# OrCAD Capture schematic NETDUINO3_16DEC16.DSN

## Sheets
1 PAGE2: size C; note: CW0057
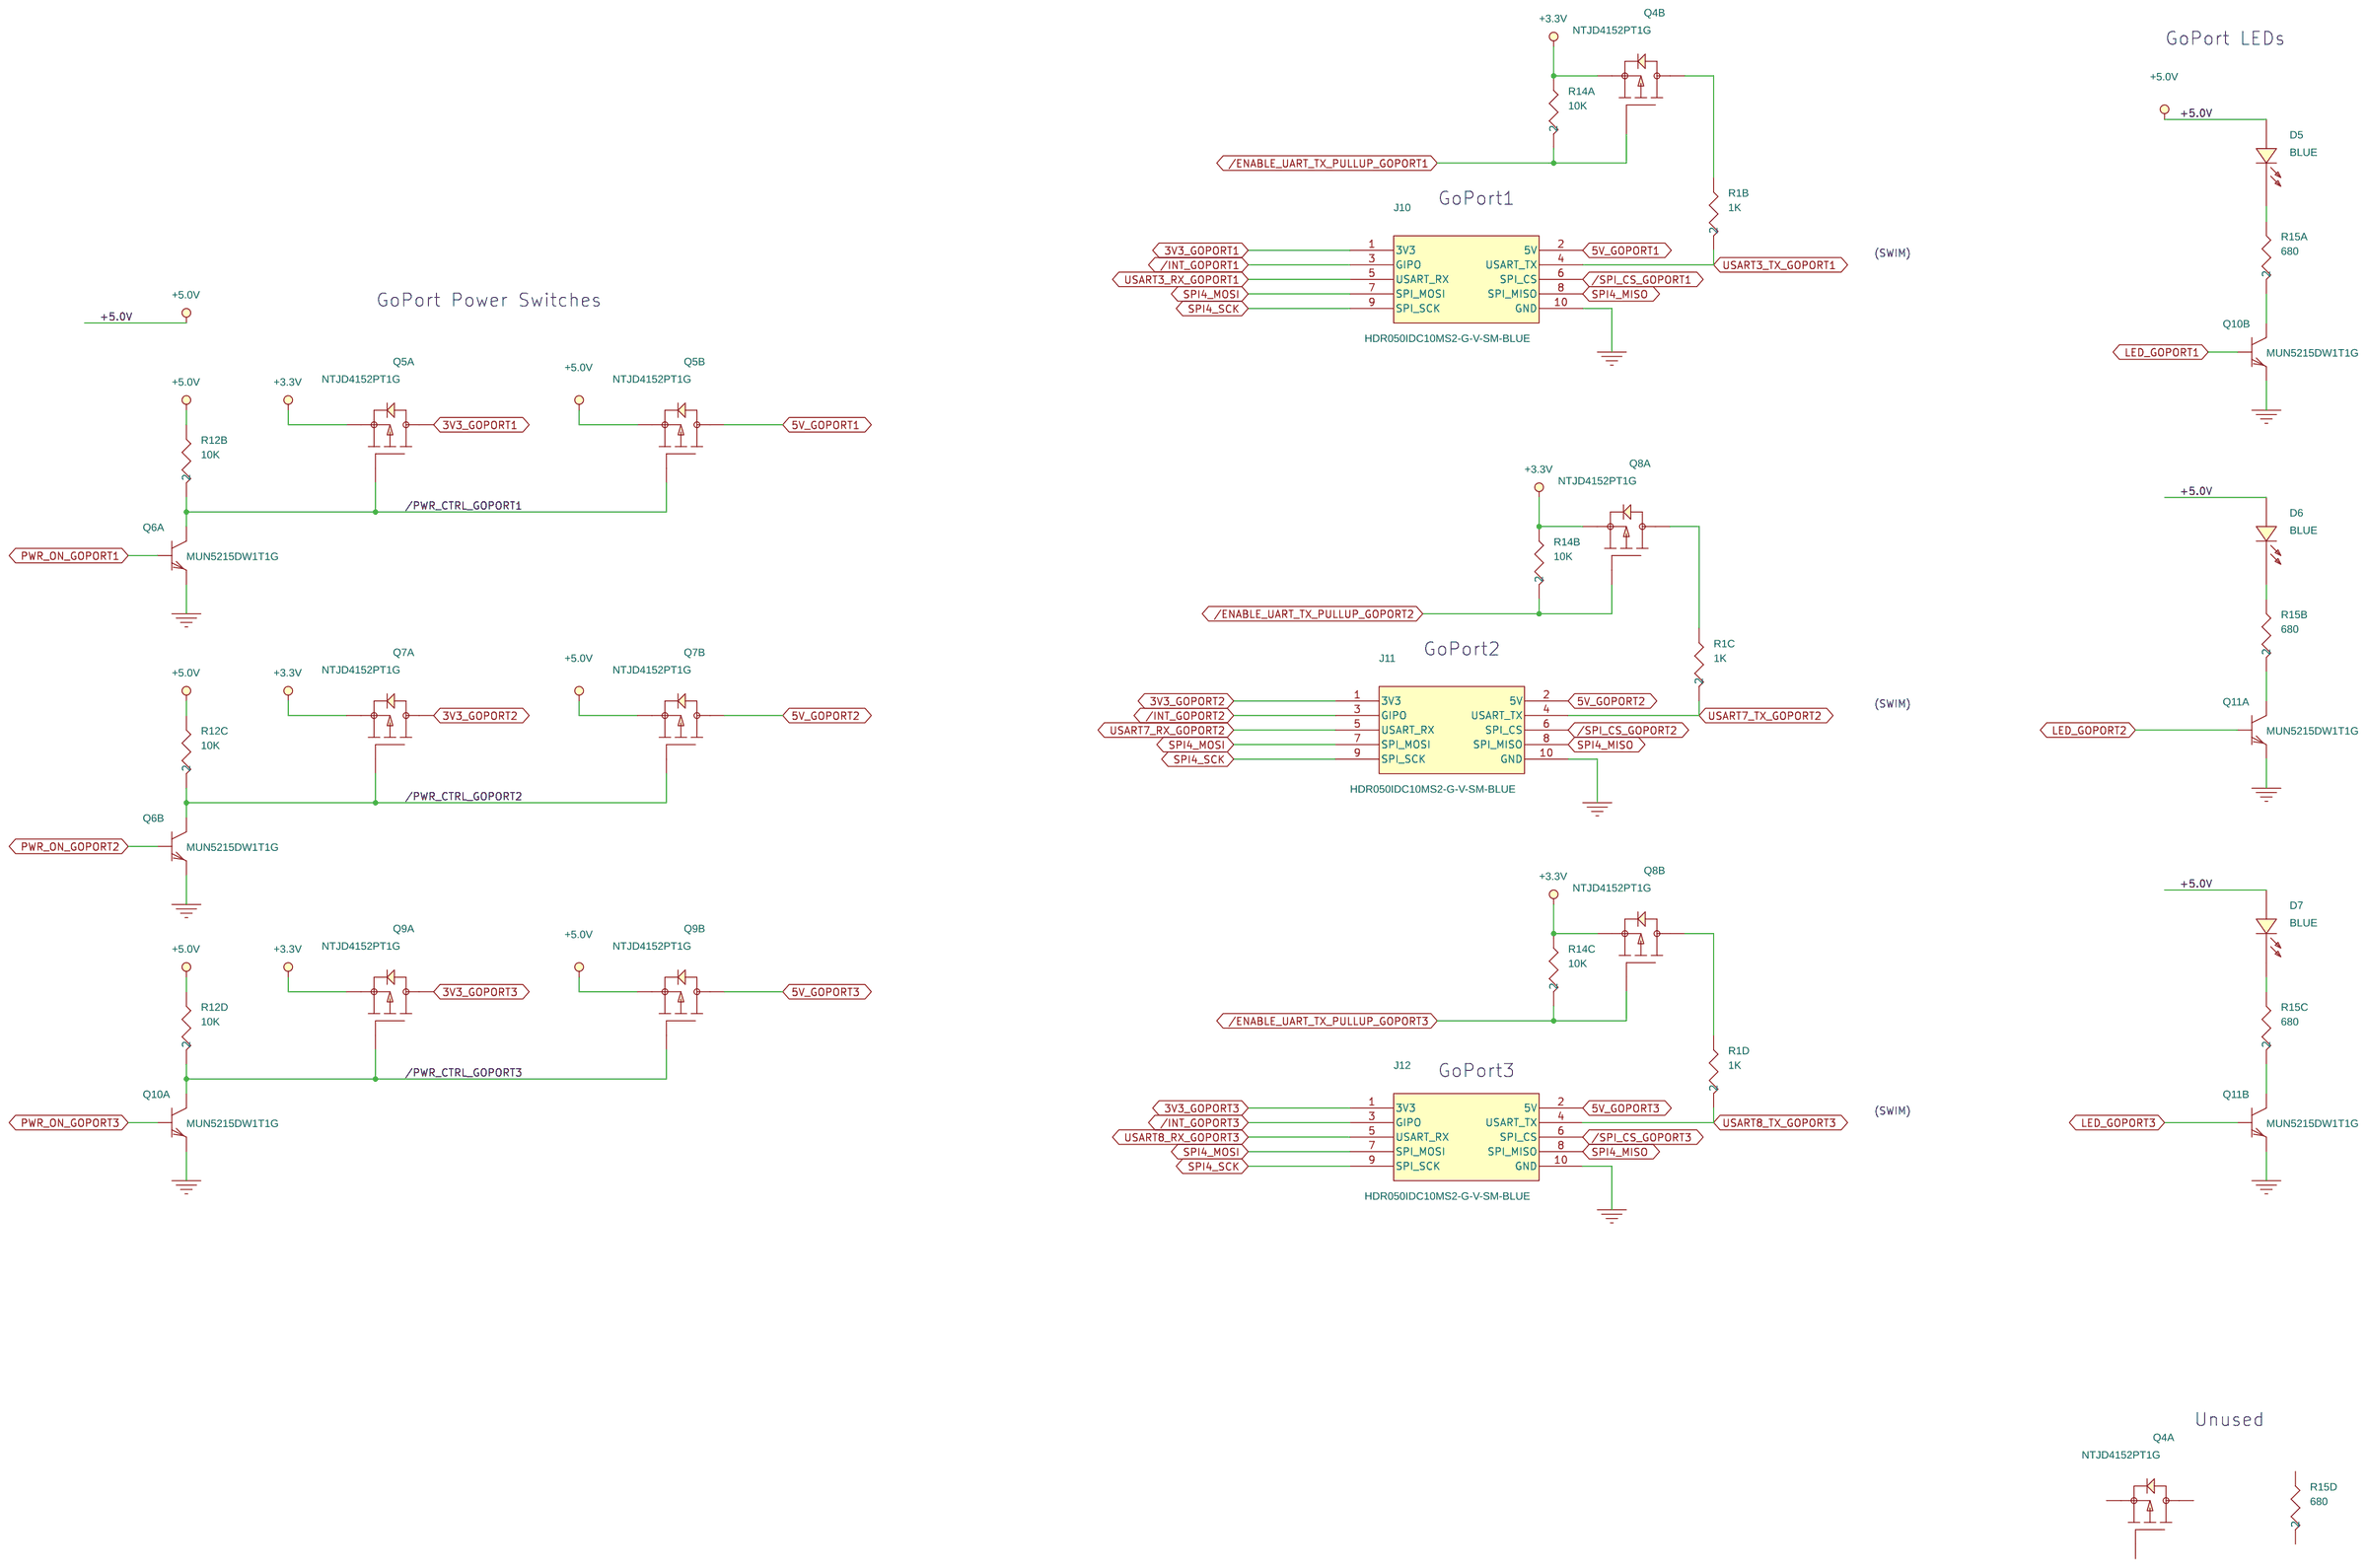
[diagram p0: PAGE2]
2 PAGE1: size C
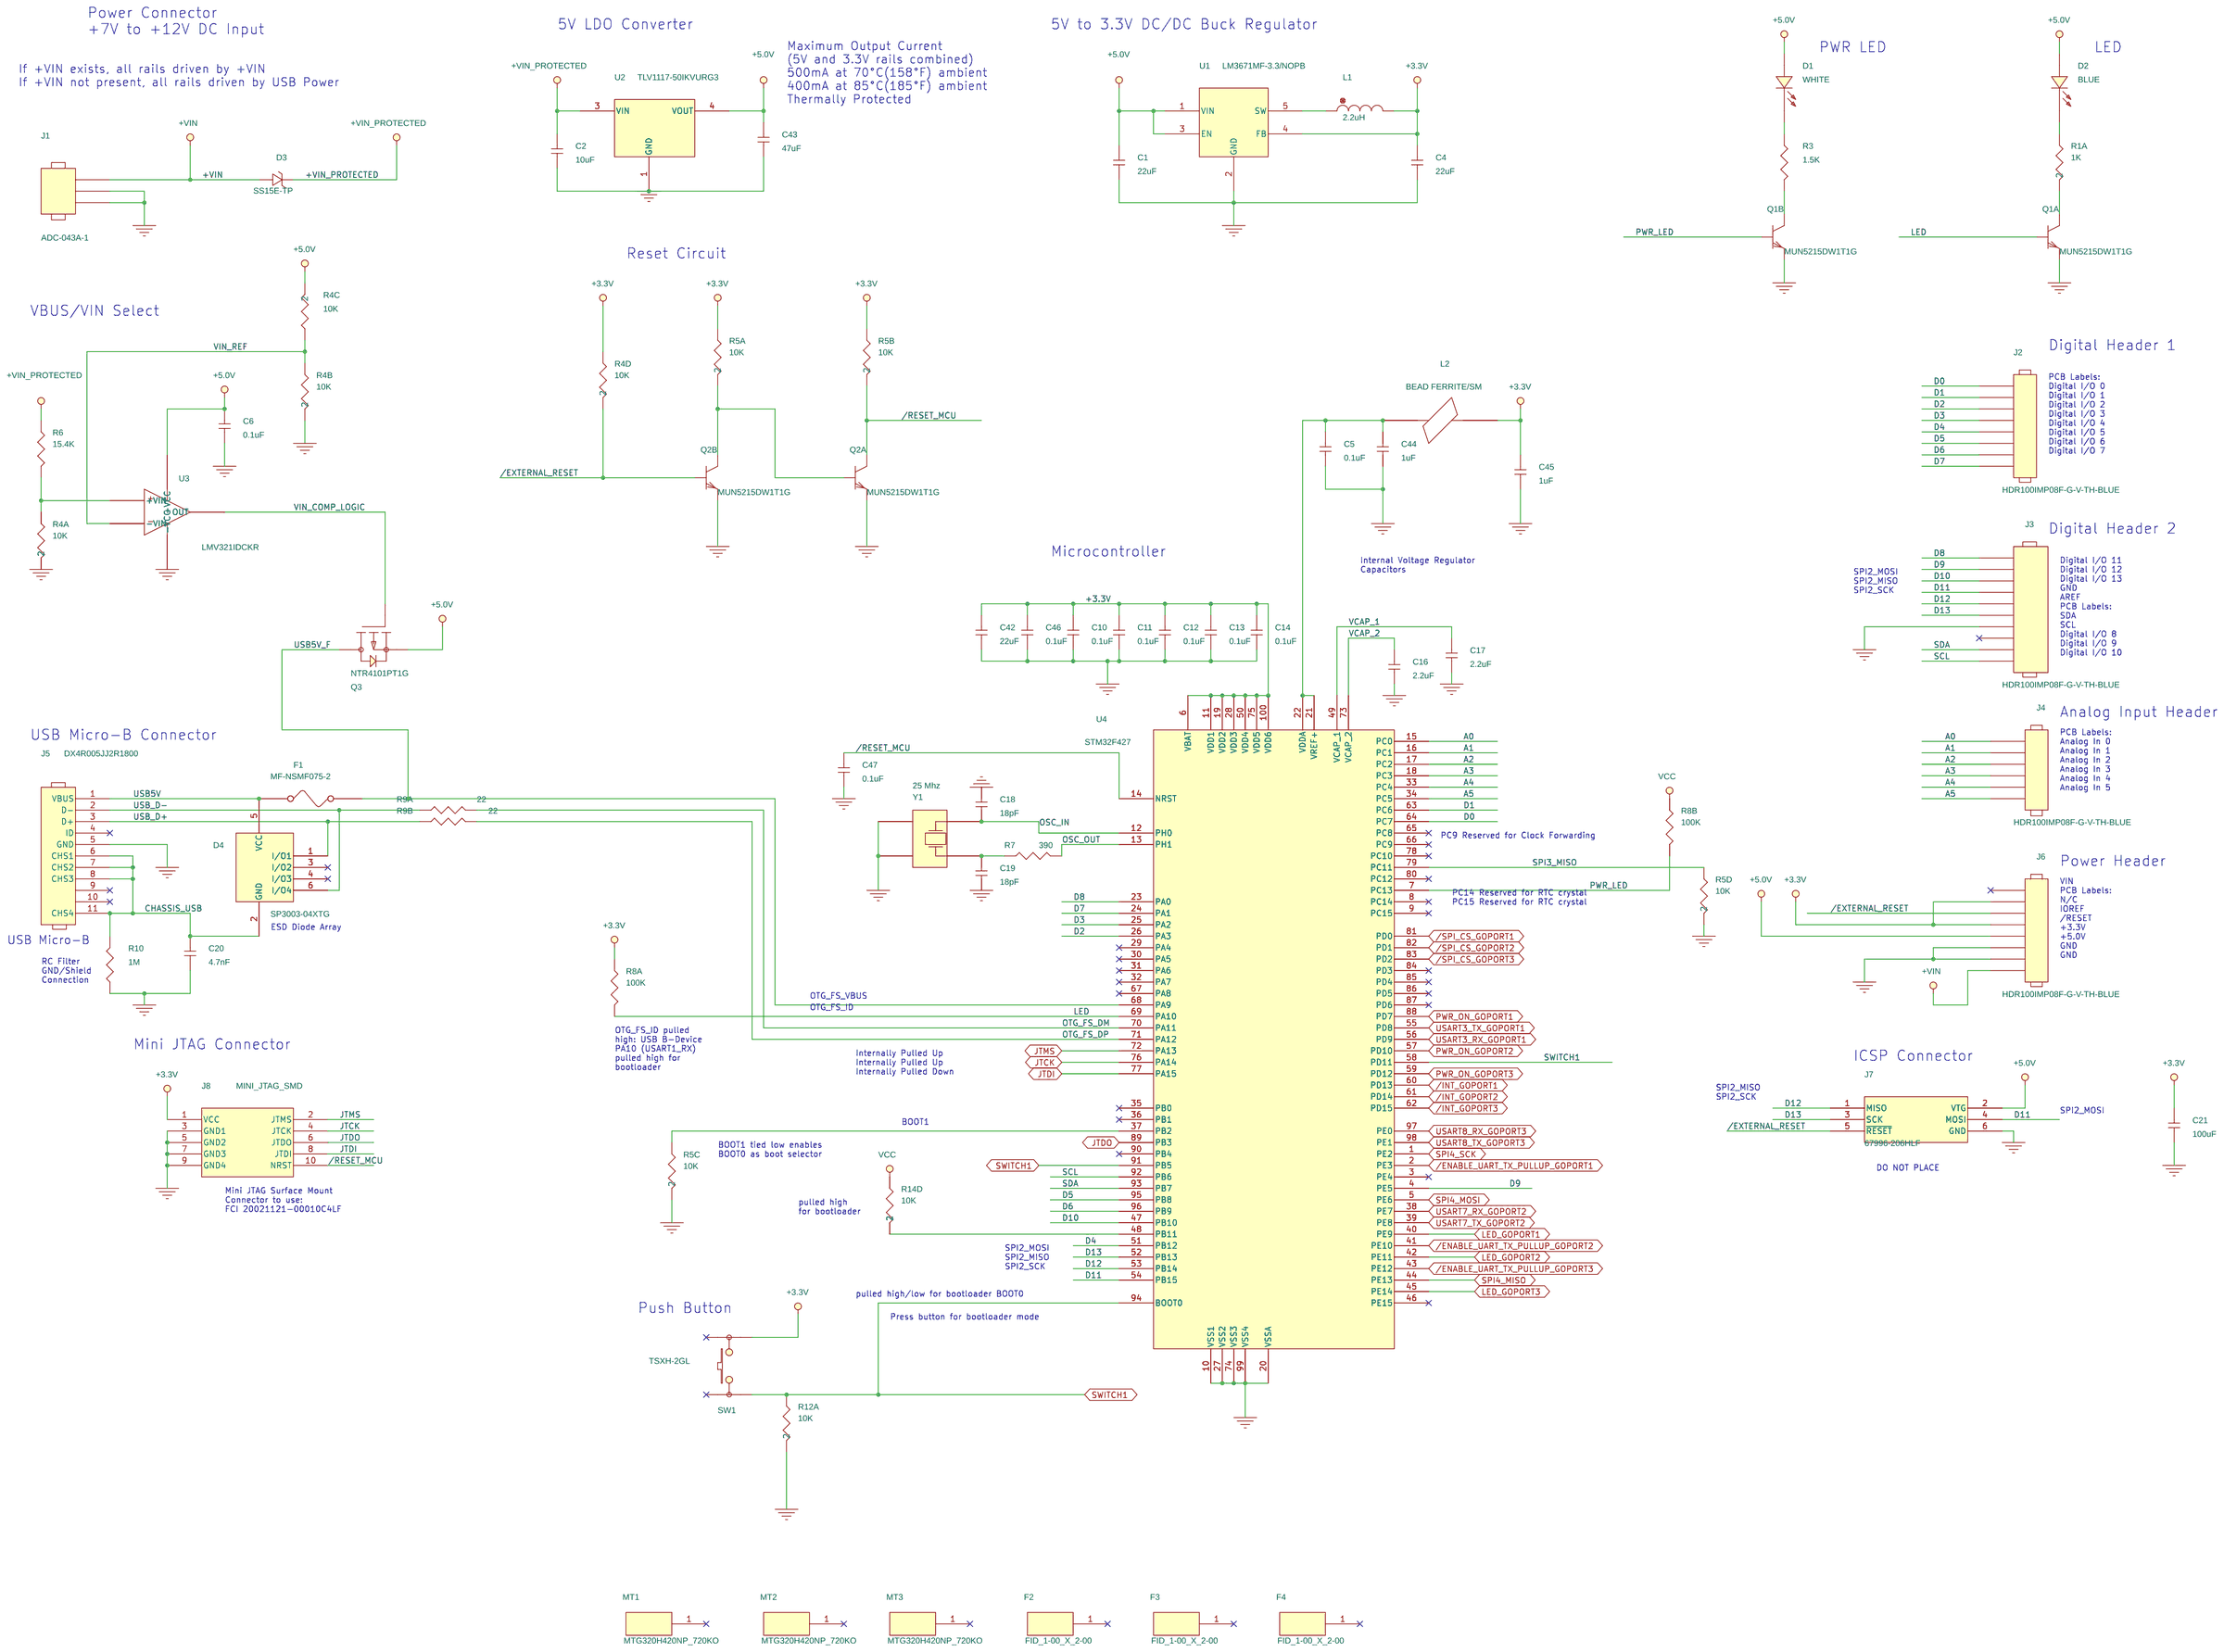
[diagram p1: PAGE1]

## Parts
sheet PAGE1
C1  22uF  [CAPC3216X180N]
C2  10uF  [CAPC2012X125N]
C4  22uF  [CAPC2012X125N]
C5  0.1uF  [CAPC1608X90N]
C6  0.1uF  [CAPC1608X90N]
C10  0.1uF  [CAPC1608X90N]
C11  0.1uF  [CAPC1608X90N]
C12  0.1uF  [CAPC1608X90N]
C13  0.1uF  [CAPC1608X90N]
C14  0.1uF  [CAPC1608X90N]
C16  2.2uF  [CAPC1608X90N]
C17  2.2uF  [CAPC1608X90N]
C18  18pF  [CAPC1608X90N]
C19  18pF  [CAPC1608X90N]
C20  4.7nF  [CAPC1005X55N]
C21  100uF  [CAPMP6032X280N]
C42  22uF  [CAPC2012X125N]
C43  47uF  [F931A476MBA]
C44  1uF  [CAPC1005X55N]
C45  1uF  [CAPC1005X55N]
C46  0.1uF  [CAPC1608X90N]
C47  0.1uF  [CAPC1608X90N]
D1  WHITE  [LEDC2012X110N]
D2  BLUE  [LEDC2012X110N]
D3  SS15E-TP  [SS15-TP]
D4  SP3003-04XTG  [SP3003-04XTG]
F1  MF-NSMF075-2  [RESC3216X100N]
F2  FID_1-00_X_2-00  [FID_1-00_X_2-00]
F3  FID_1-00_X_2-00  [FID_1-00_X_2-00]
F4  FID_1-00_X_2-00  [FID_1-00_X_2-00]
J1  ADC-043A-1  [ADC-002A-1]
J2  HDR100IMP08F-G-V-TH-BLUE  [HDR100IMP08F-G-V-TH]
J3  HDR100IMP08F-G-V-TH-BLUE  [HDR100IMP10F-G-V-TH]
J4  HDR100IMP08F-G-V-TH-BLUE  [HDR100IMP06F-G-V-TH]
J5  DX4R005JJ2R1800  [DX4R005JJ2R1800]
J6  HDR100IMP08F-G-V-TH-BLUE  [HDR100IMP08F-G-V-TH]
J7  67996-206HLF  [67996-206HLF]
J8  MINI_JTAG_SMD  [MINI_JTAG_SMD]
L1  2.2uH  [LQH3NPN2R2NM0L]
L2  BEAD FERRITE/SM  [INDC1005X55N]
MT1  MTG320H420NP_720KO  [MTG320H420NP_720KO]
MT2  MTG320H420NP_720KO  [MTG320H420NP_720KO]
MT3  MTG320H420NP_720KO  [MTG320H420NP_720KO]
Q1  MUN5215DW1T1G  [MUN5215DW1T1G]  (sections A,B)
Q2  MUN5215DW1T1G  [MUN5215DW1T1G]  (sections A,B)
Q3  NTR4101PT1G  [NTR4101PT1G]
R1  1K  [RESCAV50P80X160X60-8N]  (sections A,B,C,D)
R3  1.5K  [RESC1608]
R4  10K  [RESCAV80P160X320X70-8N]  (sections A,B,C,D)
R5  10K  [RESCAV80P160X320X70-8N]  (sections A,B,C,D)
R6  15.4K  [CAPC1005X55N]
R7  390  [CAPC1005X55N]
R8  100K  [EXB24V]  (sections A,B)
R9  22  [EXB24V]  (sections A,B)
R10  1M  [RESC1608]
R12  10K  [RESCAV80P160X320X70-8N]  (sections A,B,C,D)
R14  10K  [RESCAV80P160X320X70-8N]  (sections A,B,C,D)
SW1  TSXH-2GL  [TSXH-2GL]
U1  LM3671MF-3.3/NOPB  [LM3671MF]
U2  TLV1117-50IKVURG3  [TLV1117-50IKVURG3]
U3  LMV321IDCKR  [LMV321IDCKR]
U4  STM32F427  [STM32F427VIT6]
Y1  25 Mhz  [ABM3B]
sheet PAGE2
D5  BLUE  [LEDC1608X80N]
D6  BLUE  [LEDC1608X80N]
D7  BLUE  [LEDC1608X80N]
J10  HDR050IDC10MS2-G-V-SM-BLUE  [20021521-00010T1LF]
J11  HDR050IDC10MS2-G-V-SM-BLUE  [20021521-00010T1LF]
J12  HDR050IDC10MS2-G-V-SM-BLUE  [20021521-00010T1LF]
Q4  NTJD4152PT1G  [NTJD4152PT1G]  (sections A,B)
Q5  NTJD4152PT1G  [NTJD4152PT1G]  (sections A,B)
Q6  MUN5215DW1T1G  [MUN5215DW1T1G]  (sections A,B)
Q7  NTJD4152PT1G  [NTJD4152PT1G]  (sections A,B)
Q8  NTJD4152PT1G  [NTJD4152PT1G]  (sections A,B)
Q9  NTJD4152PT1G  [NTJD4152PT1G]  (sections A,B)
Q10  MUN5215DW1T1G  [MUN5215DW1T1G]  (sections A,B)
Q11  MUN5215DW1T1G  [MUN5215DW1T1G]  (sections A,B)
R15  680  [RESCAV50P80X160X60-8N]  (sections A,B,C,D)

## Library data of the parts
C1 C2 C4-C6 C10-C14 C16-C21 C42-C47 = C
D1 = LED_2
D2 D5-D7 = LED_1
D3 = D05AZ75_0
D4 = HEADER_6_0
F1 = FUSE
F2-F4 MT1-MT3 = MOUNT_HOLE
J1 = HEADER_3
J2 J6 = HEADER_8
J3 = HEADER_10
J4 = HEADER_6
J5 = HEADER_11_0
J7 = HEADER_6_1
J8 = HEADER_10_2_v2
L1 = L
L2 = BEAD_FERRITE_SM
Q1 Q2 = MUN5215DW1T1G_3
Q3 = NDF0610_TO_1
R1 R4 R5 R12 R14 R15 = RESCAV50P80X160X60-8N
R3 R6 R7 R10 = R
R8 R9 = EXB24V
SW1 = SW_PUSHBUTTON-SPST-2_0
U1 = HEADER_5_0
U2 = LM7805_TO_2
U3 = LMV321_SO
U4 = STM32F427_0
Y1 = OSC_XF: MPN: ABM3B-25.000MHZ-D2Y-T; Manufacturer: Abracon Corporation
J10-J12 = HEADER_10_2
Q4 Q5 Q7-Q9 = NTJD4152PT1G
Q6 Q10 Q11 = MUN5215DW1T1G_0

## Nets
3V3_GOPORT1: J10.1(3V3) Q5.6(DRAIN)
3V3_GOPORT2: J11.1(3V3) Q7.6(DRAIN)
3V3_GOPORT3: J12.1(3V3) Q9.6(DRAIN)
5V_GOPORT1: J10.2(5V) Q5.3(DRAIN)
5V_GOPORT2: J11.2(5V) Q7.3(DRAIN)
5V_GOPORT3: J12.2(5V) Q9.3(DRAIN)
+3.3V: C4.1 C10.1 C11.1 C12.1 C13.1 C14.1 C21.1 C42.1 C45.1 C46.1 J6.2 J6.4 J8.1(VCC) L1.2 L2.2 Q4.4(SOURCE) Q5.1(SOURCE) Q7.1(SOURCE) Q8.1(SOURCE) Q8.4(SOURCE) Q9.1(SOURCE) R4.4 R5.1 R5.2 R8.1 R8.2 R14.1 R14.2 R14.3 R14.4 SW1.2 U1.4(FB) U4.6(VBAT) U4.11(VDD1) U4.19(VDD2) U4.28(VDD3) U4.50(VDD4) U4.75(VDD5) U4.100(VDD6)
+5.0V: C1.1 C6.1 C43.1 D1.A(ANODE) D2.A(ANODE) D5.A(ANODE) D6.A(ANODE) D7.A(ANODE) J6.5 J7.2(VTG) Q3.2(SOURCE) Q5.4(SOURCE) Q7.4(SOURCE) Q9.4(SOURCE) R4.6(2) R12.2 R12.3 R12.4 U1.1(VIN) U1.3(EN) U2.4(VOUT) U3.5(+VCC)
+VIN: D3.A(1) J1.1 J6.8
+VIN_PROTECTED: C2.1 D3.C(2) R6.1 U2.3(VIN)
VIN_COMP_LOGIC: Q3.1(GATE) U3.4(OUT)
VIN_REF: R4.2 R4.3 U3.3(-VIN)
0: C1.2 C2.2 C4.2 C5.2 C6.2 C10.2 C11.2 C12.2 C13.2 C14.2 C16.2 C17.2 C18.2 C19.2 C20.1 C21.2 C42.2 C43.2 C44.2 C45.2 C46.2 C47.2 J1.2 J1.3 J3.7 J5.5(GND) J6.6 J6.7 J7.6(GND) J8.3(GND1) J8.5(GND2) J8.7(GND3) J8.9(GND4) J10.10(GND) J11.10(GND) J12.10(GND) Q1.1(e) Q1.4(e) Q2.1(e) Q2.4(e) Q6.1(e) Q6.4(e) Q10.1(e) Q10.4(e) Q11.1(e) Q11.4(e) R4.7(2) R4.8(2) R5.5(2) R5.6(2) R10.1 R12.8(2) U1.2(GND) U2.1(GND) U3.2(-VCC) U4.10(VSS1) U4.20(VSSA) U4.27(VSS2) U4.74(VSS3) U4.99(VSS4) Y1.2 Y1.4
/ENABLE_UART_TX_PULLUP_GOPORT1: Q4.5(GATE) R14.8(2) U4.2(PE3)
/ENABLE_UART_TX_PULLUP_GOPORT2: Q8.2(GATE) R14.7(2) U4.41(PE10)
/ENABLE_UART_TX_PULLUP_GOPORT3: Q8.5(GATE) R14.6(2) U4.43(PE12)
/EXTERNAL_RESET: J6.3 J7.5(~{RESET}) Q2.5(b) R4.5(2)
/INT_GOPORT1: J10.3(GIPO) U4.60(PD13)
/INT_GOPORT2: J11.3(GIPO) U4.61(PD14)
/INT_GOPORT3: J12.3(GIPO) U4.62(PD15)
/PWR_CTRL_GOPORT1: Q5.2(GATE) Q5.5(GATE) Q6.3(c) R12.7(2)
/PWR_CTRL_GOPORT2: Q6.6(c) Q7.2(GATE) Q7.5(GATE) R12.6(2)
/PWR_CTRL_GOPORT3: Q9.2(GATE) Q9.5(GATE) Q10.3(c) R12.5(2)
/RESET_MCU: C47.1 J8.10(NRST) Q2.6(c) R5.7(2) U4.14(NRST)
/SPI_CS_GOPORT1: J10.6(SPI_CS) U4.81(PD0)
/SPI_CS_GOPORT2: J11.6(SPI_CS) U4.82(PD1)
/SPI_CS_GOPORT3: J12.6(SPI_CS) U4.83(PD2)
A0: J4.1 U4.15(PC0)
A1: J4.2 U4.16(PC1)
A2: J4.3 U4.17(PC2)
A3: J4.4 U4.18(PC3)
A4: J4.5 U4.33(PC4)
A5: J4.6 U4.34(PC5)
CHASSIS_USB: C20.2 D4.2(GND) J5.6(CHS1) J5.7(CHS2) J5.8(CHS3) J5.11(CHS4) R10.2
D0: J2.1 U4.64(PC7)
D1: J2.2 U4.63(PC6)
D2: J2.3 U4.26(PA3)
D3: J2.4 U4.25(PA2)
D4: J2.5 U4.51(PB12)
D5: J2.6 U4.95(PB8)
D6: J2.7 U4.96(PB9)
D7: J2.8 U4.24(PA1)
D8: J3.1 U4.23(PA0)
D9: J3.2 U4.4(PE5)
D10: J3.3 U4.47(PB10)
D11: J3.4 J7.4(MOSI) U4.54(PB15)
D12: J3.5 J7.1(MISO) U4.53(PB14)
D13: J3.6 J7.3(SCK) U4.52(PB13)
JTCK: J8.4(JTCK) U4.76(PA14)
JTDI: J8.8(JTDI) U4.77(PA15)
JTDO: J8.6(JTDO) U4.89(PB3)
JTMS: J8.2(JTMS) U4.72(PA13)
LED: Q1.2(b) R8.4(2) U4.69(PA10)
LED_GOPORT1: Q10.2(b) U4.40(PE9)
LED_GOPORT2: Q11.5(b) U4.42(PE11)
LED_GOPORT3: Q11.2(b) U4.45(PE14)
OSC_IN: C18.1 U4.12(PH0) Y1.3
OSC_OUT: R7.2 U4.13(PH1)
OTG_FS_DM: R9.4(2) U4.70(PA11)
OTG_FS_DP: R9.3(2) U4.71(PA12)
PWR_LED: Q1.5(b) R8.3(2) U4.7(PC13)
PWR_ON_GOPORT1: Q6.5(b) U4.88(PD7)
PWR_ON_GOPORT2: Q6.2(b) U4.57(PD10)
PWR_ON_GOPORT3: Q10.5(b) U4.59(PD12)
SCL: J3.10 U4.92(PB6)
SDA: J3.9 U4.93(PB7)
SPI3_MISO: R5.4 U4.79(PC11)
SPI4_MISO: J10.8(SPI_MISO) J11.8(SPI_MISO) J12.8(SPI_MISO) U4.44(PE13)
SPI4_MOSI: J10.7(SPI_MOSI) J11.7(SPI_MOSI) J12.7(SPI_MOSI) U4.5(PE6)
SPI4_SCK: J10.9(SPI_SCK) J11.9(SPI_SCK) J12.9(SPI_SCK) U4.1(PE2)
SWITCH1: R12.1 SW1.4 U4.58(PD11) U4.91(PB5) U4.94(BOOT0)
USART3_RX_GOPORT1: J10.5(USART_RX) U4.56(PD9)
USART3_TX_GOPORT1: J10.4(USART_TX) R1.7(2) U4.55(PD8)
USART7_RX_GOPORT2: J11.5(USART_RX) U4.38(PE7)
USART7_TX_GOPORT2: J11.4(USART_TX) R1.6(2) U4.39(PE8)
USART8_RX_GOPORT3: J12.5(USART_RX) U4.97(PE0)
USART8_TX_GOPORT3: J12.4(USART_TX) R1.5(2) U4.98(PE1)
USB5V: D4.5(VCC) F1.1 J5.1(VBUS)
USB5V_F: F1.2 Q3.3(DRAIN) U4.68(PA9)
USB_D+: D4.1(I/O1) J5.3(D+) R9.2
USB_D-: D4.6(I/O4) J5.2(D-) R9.1
VCAP_1: C17.1 U4.49(VCAP_1)
VCAP_2: C16.1 U4.73(VCAP_2)
N62667: R4.1 R6.2 U3.1(+VIN)
N62753: Q2.2(b) Q2.3(c) R5.8(2)
N62779: L1.1 U1.5(SW)
N62801: D2.C(CATHODE) R1.1
N62841: R5.3 U4.37(PB2)
N63081: C5.1 C44.1 L2.1 U4.21(VREF+) U4.22(VDDA)
N74908: Q1.6(c) R1.8(2)
N77511: D1.C(CATHODE) R3.1
N77515: Q1.3(c) R3.2
N197515: Q10.6(c) R15.8(2)
N197535: D5.C(CATHODE) R15.1
N197921: Q11.3(c) R15.7(2)
N197949: D6.C(CATHODE) R15.2
N198166: Q11.6(c) R15.6(2)
N198194: D7.C(CATHODE) R15.3
N199051: Q4.3(DRAIN) R1.2
N202411: Q8.6(DRAIN) R1.3
N203046: Q8.3(DRAIN) R1.4
N249435: R14.5(2) U4.48(PB11)
N261857: C19.1 R7.1 Y1.1

Not connected (* = marked no-connect by the designer): D4 3(I/O2)* 4(I/O3)*; F2 1*; F3 1*; F4 1*; J3 8*; J5 4(ID)* 9* 10*; J6 1*; MT1 1*; MT2 1*; MT3 1*; Q4 1(SOURCE) 2(GATE) 6(DRAIN); R15 4 5(2); SW1 1* 3*; U4 3(PE4)* 8(PC14)* 9(PC15)* 29(PA4)* 30(PA5)* 31(PA6)* 32(PA7)* 35(PB0)* 36(PB1)* 46(PE15)* 65(PC8)* 66(PC9)* 67(PA8)* 78(PC10)* 80(PC12)* 84(PD3)* 85(PD4)* 86(PD5)* 87(PD6)* 90(PB4)*

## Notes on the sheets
sheet 1
- GoPort LEDs
- GoPort1
- (SWIM)
- GoPort Power Switches
- GoPort2
- (SWIM)
- GoPort3
- (SWIM)
- Unused
sheet 2
- Power Connector
  +7V to +12V DC Input
- 5V LDO Converter
- 5V to 3.3V DC/DC Buck Regulator
- Maximum Output Current
  (5V and 3.3V rails combined)
  500mA at 70°C(158°F) ambient
  400mA at 85°C(185°F) ambient
  Thermally Protected
- PWR LED
- LED
- If +VIN exists, all rails driven by +VIN
  If +VIN not present, all rails driven by USB Power
- Reset Circuit
- VBUS/VIN Select
- Digital Header 1
- PCB Labels:
  Digital I/O 0
  Digital I/O 1
  Digital I/O 2
  Digital I/O 3
  Digital I/O 4
  Digital I/O 5
  Digital I/O 6
  Digital I/O 7
- Digital Header 2
- Microcontroller
- Internal Voltage Regulator
  Capacitors
- Digital I/O 11
  Digital I/O 12
  Digital I/O 13
  GND
  AREF
  PCB Labels:
  SDA
  SCL
  Digital I/O 8
  Digital I/O 9
  Digital I/O 10
- SPI2_MOSI
  SPI2_MISO
  SPI2_SCK
- Analog Input Header
- USB Micro-B Connector
- PCB Labels:
  Analog In 0
  Analog In 1
  Analog In 2
  Analog In 3
  Analog In 4
  Analog In 5
- PC9 Reserved for Clock Forwarding
- Power Header
- VIN
  PCB Labels:
  N/C
  IOREF
  /RESET
  +3.3V
  +5.0V
  GND
  GND
- PC14 Reserved for RTC crystal
  PC15 Reserved for RTC crystal
- ESD Diode Array
- USB Micro-B
- RC Filter
  GND/Shield
  Connection
- OTG_FS_VBUS
- OTG_FS_ID
- OTG_FS_ID pulled
  high: USB B-Device
  PA10 (USART1_RX)
  pulled high for
  bootloader
- Mini JTAG Connector
- Internally Pulled Up
  Internally Pulled Up
  Internally Pulled Down
- ICSP Connector
- SPI2_MISO
  SPI2_SCK
- SPI2_MOSI
- BOOT1
- BOOT1 tied low enables
  BOOT0 as boot selector
- DO NOT PLACE
- Mini JTAG Surface Mount
  Connector to use:
  FCI 20021121-00010C4LF
- pulled high
  for bootloader
- SPI2_MOSI
  SPI2_MISO
  SPI2_SCK
- pulled high/low for bootloader BOOT0
- Push Button
- Press button for bootloader mode
